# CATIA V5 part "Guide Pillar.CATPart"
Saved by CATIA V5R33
Part number: Guide Pillar
Bounding box of the stored display mesh (mm): x 82.5 to 107.5, y 17.69 to 42.31, z 0 to 200
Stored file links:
  D:\PROJECTS\Project 2023\CATIA V5 6R 2023\Resources\Tutorial Files\c12_catia_v5_6r2023_tut\c12tut2\Guide Pillar.CATPart
  E:\_Deepak\2017_Deepak\CATIA\Resources\Tutorial Files\Tutorials\c12_catia_v5_6r2015_tut\c12tut2\Assembly_cat_v5-6r2016.CATProduct
  D:\PROJECTS\Project 2021\US EDITION\CATIA V5 6R 2021\Resources\Tutorial Files\c12_catia_v5_6r2021_tut\c12tut2\Bottom Plate.CATPart
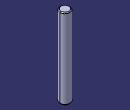
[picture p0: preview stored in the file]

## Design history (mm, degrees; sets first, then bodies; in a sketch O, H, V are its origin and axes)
Set1
  DatumSurface1: linked copy from another document
  DatumCurve1: linked copy from another document
Body1 (main body)
  Sketch1 on face of DatumSurface1, origin (0, 0, 0), H (1, 0, 0), V (0, 1, 0)
    projected circle E1 centre (95, 30) radius 12.5 from edge of DatumCurve1
  Pad1: profile Sketch1, direction (0, 0, 1), length 200
  Chamfer1: length 2, angle 45, on edge [face of Pad1 | face of Pad1] (x2)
